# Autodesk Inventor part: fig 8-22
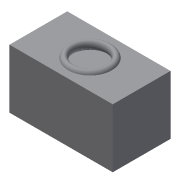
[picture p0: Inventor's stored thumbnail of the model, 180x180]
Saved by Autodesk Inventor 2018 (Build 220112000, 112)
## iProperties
Created: 2011-07
Part Number: fig 8-22
Material: Generic
Document SubType Name: Modeling
Designer: CadCim
Density: 1 g/cm^3
Appearance: Default
Author: CadCim
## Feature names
1. Extrusion1
2. Extrusion2
3. Sweep1
## Parameters: d0 = 14.25 mm, d1 = 0, d2 = 1.5 mm, d3 = 0, d4 = -4.25 mm, d5 = 0, d6 = 0
